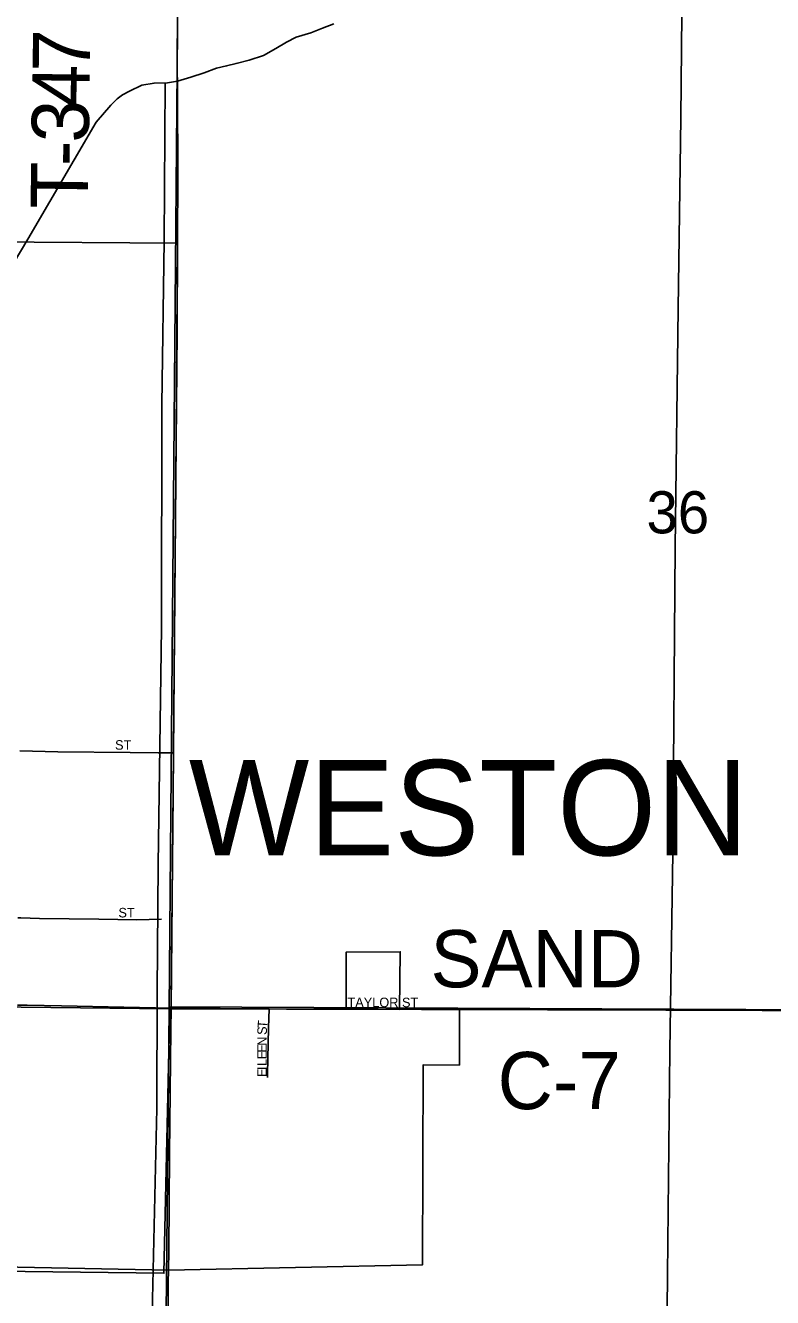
# Model space of a CAD drawing. Extents: x 1443599 to 1910620, y 1028088 to 1361369.
# Drawn here: x 1614403 to 1618321, y 1218862 to 1225536 of the extents above; entities that cross this region are included whole.
import ezdxf

# ---------------------------------------------------------------- set-up
doc = ezdxf.new("R2010")
doc.units = 0
for name, color, linetype in [('GM_X_City_Street', 7, 'Continuous'), ('GM_X_City_Street_Text', 7, 'Continuous'), ('GM_X_Corporation', 7, 'Continuous'), ('GM_X_Corporation_Text', 7, 'Continuous'), ('GM_X_County_Road', 7, 'Continuous'), ('GM_X_County_Road_Text', 7, 'Continuous'), ('GM_X_Minor_River', 7, 'Continuous'), ('GM_X_Section', 7, 'Continuous'), ('GM_X_Section_Text', 7, 'Continuous'), ('GM_X_State_Route', 7, 'Continuous'), ('GM_X_Township', 7, 'Continuous'), ('GM_X_Township_Road_Text', 7, 'Continuous')]:
    doc.layers.add(name, color=color, linetype=linetype)

msp = doc.modelspace()

# ---------------------------------------------------------------- linework, layer by layer
at = {"layer": 'GM_X_City_Street'}
for points in [[(1614372.6, 1221730.2), (1614573.4, 1221725.7), (1614951.5, 1221721.1), (1615099.4, 1221719.8), (1615148.7, 1221719.9), (1615179, 1221720)], [(1614362.1, 1220854.6), (1614379.1, 1220854.3), (1614477, 1220851.2), (1614787.7, 1220847.2), (1614987.8, 1220844), (1615116.2, 1220846.5)], [(1614360.3, 1220396.1), (1614412.1, 1220395.2), (1614592, 1220392.7), (1614919.4, 1220386.2), (1615166.8, 1220380.6)], [(1615671.6, 1220017.2), (1615671.6, 1220033.3), (1615678.1, 1220276.7), (1615681.8, 1220376.3)], [(1616085.3, 1220374.8), (1616136.9, 1220374.5), (1616253.7, 1220374.3), (1616364.3, 1220373.8)]]:
    msp.add_lwpolyline(points, dxfattribs=at)
at = {"layer": 'GM_X_Corporation'}
msp.add_lwpolyline([(1614197, 1224401.7), (1615200.1, 1224394.6), (1615191.8, 1223150.4), (1615179, 1221720), (1615166.8, 1220380.6), (1615681.8, 1220376.3), (1616085.3, 1220374.8), (1616084.9, 1220674.1), (1616368.6, 1220676.3), (1616364.3, 1220373.8), (1616679, 1220375.2), (1616679.2, 1220082.1), (1616488.9, 1220083.4), (1616484.8, 1219033.3), (1615152.7, 1219006.6), (1612518, 1219058.9)], dxfattribs=at)
at = {"layer": 'GM_X_County_Road'}
for points in [[(1615166.8, 1220380.6), (1615213.5, 1220380.2), (1615379.2, 1220378.7), (1615511.8, 1220376.9), (1615681.8, 1220376.3)], [(1615681.8, 1220376.3), (1615772.8, 1220375.9), (1616085.3, 1220374.8)], [(1616364.3, 1220373.8), (1616679.1, 1220375.2)], [(1616679.1, 1220375.2), (1616859.4, 1220374.6), (1617138.4, 1220373.3), (1617368.2, 1220372.1), (1617581.7, 1220372.1), (1617762.2, 1220370.4), (1618123.4, 1220369.7), (1618697.9, 1220362.8), (1618862.2, 1220361.8), (1618928.3, 1220363.4), (1618945.4, 1220365.2)]]:
    msp.add_lwpolyline(points, dxfattribs=at)
at = {"layer": 'GM_X_Minor_River'}
for points in [[(1617853.3, 1226327.9), (1617840.1, 1225049.4), (1617825.5, 1224051.8), (1617810.7, 1222799.8), (1617798, 1221193.2), (1617782.7, 1220157.6), (1617771.2, 1218983.8), (1617758, 1217707.9), (1617748.7, 1216428), (1617736.7, 1215352.4), (1617735.8, 1213978.3), (1617725.2, 1212506.2), (1617715, 1211422.7), (1617702.4, 1210197), (1617703.6, 1209429.7), (1617680.8, 1208428.5), (1617671.9, 1207420.9), (1617660.9, 1206527.6), (1617638.1, 1205167.5)], [(1616020, 1225544.6), (1615961.5, 1225521.6), (1615899, 1225496.6), (1615822.6, 1225473.8), (1615772.1, 1225448.6), (1615715.4, 1225415.5), (1615650.7, 1225378.5), (1615576.2, 1225353.7), (1615507.9, 1225336.8), (1615457.6, 1225323.6), (1615405.3, 1225312.5), (1615340.8, 1225287.5), (1615270.4, 1225264.7), (1615199.9, 1225243.8), (1615147.7, 1225234.7), (1615077.6, 1225233.8), (1615013.4, 1225222.9), (1614948.8, 1225191.9), (1614912.4, 1225172.5)], [(1611444.7, 1220885.3), (1611444.3, 1221099.7), (1611143.6, 1221684), (1611133, 1222970.4), (1611135.9, 1223023.6), (1611156.5, 1223062.1), (1611184.5, 1223072.3), (1611302.9, 1223075.5), (1611951.5, 1223059.9), (1612608.1, 1223046.3), (1613458.9, 1223029.6), (1613668.1, 1223322.5), (1613735.4, 1223275.2), (1614133, 1223943.6), (1614415.2, 1224415.6), (1614773.8, 1225028.6), (1614851.4, 1225117.5), (1614884, 1225151), (1614912.4, 1225172.5)], [(1615135.5, 1225234.5), (1615129.9, 1224405.5), (1615117.6, 1223546.2), (1615116.2, 1222376.2), (1615099.6, 1221134.4), (1615094.5, 1220467.4), (1615092.3, 1219854.4), (1615068.3, 1218777), (1615067.4, 1217637.2), (1615056, 1216713.9), (1615044.3, 1215650.5), (1615036.1, 1214564.9), (1615022.5, 1213507.5), (1615006.2, 1212293.8)]]:
    msp.add_lwpolyline(points, dxfattribs=at)
at = {"layer": 'GM_X_Section'}
for points in [[(1609861.1, 1225754.9), (1615202.5, 1225719.6), (1615157.1, 1220376.3), (1609876.1, 1220436.7), (1609830.1, 1220437.4)], [(1615202.5, 1225719.6), (1620518, 1225686.7), (1620446.9, 1220363.7), (1615157.1, 1220376.3)], [(1615157.1, 1220376.3), (1615104, 1215053), (1609835, 1215109.4), (1609876.1, 1220436.7)], [(1620446.9, 1220363.7), (1620417.2, 1215002), (1619967.5, 1215036.6), (1615104, 1215053), (1615157.1, 1220376.3)]]:
    msp.add_lwpolyline(points, close=True, dxfattribs=at)
at = {"layer": 'GM_X_State_Route'}
for points in [[(1615200.1, 1224394.6), (1615202.2, 1224762.6), (1615200.9, 1225173.1), (1615199.1, 1225353.8), (1615200.5, 1225583.7)], [(1615166.8, 1220380.6), (1615168, 1220616.1), (1615176.8, 1221501.9), (1615179, 1221720), (1615181.3, 1221944.7), (1615184.6, 1222371.2), (1615198.9, 1223929.6), (1615200.1, 1224394.6)], [(1615152.7, 1219006.6), (1615154.4, 1219107.5), (1615158.7, 1219613.6), (1615165.4, 1220266.6), (1615166.8, 1220380.6)], [(1615085.8, 1212392.6), (1615089.7, 1212868.6), (1615093.7, 1213213.2), (1615097.7, 1213672.7), (1615098.4, 1213919), (1615101.7, 1214115.8), (1615107.4, 1214723.1), (1615112.1, 1215055.7), (1615114.1, 1215199), (1615118.6, 1215510.9), (1615125.8, 1215888.3), (1615131.6, 1216495.5), (1615135.6, 1217070), (1615138.4, 1217250.5), (1615145.6, 1218186), (1615151.6, 1218941), (1615152.7, 1219006.6)]]:
    msp.add_lwpolyline(points, dxfattribs=at)
at = {"layer": 'GM_X_Township'}
for points in [[(1618936.9, 1220370.1), (1615159.9, 1220387.8), (1615128.7, 1218989.2), (1612506.9, 1219021.2), (1609877.9, 1219061.7), (1609890.3, 1220443.7), (1609839.9, 1220446.6), (1604546.9, 1220492.4), (1601901.6, 1220535), (1599194, 1220561.1), (1593741, 1220583.6), (1592199, 1220592.6), (1588366.5, 1220614.2), (1588383.5, 1221551.2), (1588462.3, 1225902.2), (1593947.1, 1225870.7), (1595282.7, 1225862.3), (1595353.6, 1231166.2), (1599299.9, 1231150.3), (1599313.7, 1233747.6), (1604642.8, 1233717.2), (1604665.8, 1234694.9)], [(1588234.4, 1188702.7), (1588255.8, 1194003.1), (1588277.4, 1199332.4), (1588320.4, 1204610.1), (1588324.6, 1204799.5), (1588321.6, 1209947.2), (1588321.9, 1210027.8), (1588344.4, 1215354.3), (1588366.5, 1220614.2), (1592199, 1220592.6), (1593741, 1220583.6), (1599194, 1220561.1), (1601901.6, 1220535), (1604546.9, 1220492.4), (1609839.9, 1220446.6), (1609890.3, 1220443.7), (1609877.9, 1219061.7), (1612506.9, 1219021.2), (1615128.7, 1218989.2), (1615159.9, 1220387.8), (1618936.9, 1220370.1)]]:
    msp.add_lwpolyline(points, dxfattribs=at)

# ---------------------------------------------------------------- texts
at = {"layer": 'GM_X_City_Street_Text'}
for s, rotation, p in [('ST', 0.00001, (1614872.9, 1221736.3)), ('ST', 0.00001, (1614890.5, 1220856.4)), ('TAYLOR ST', 0.00001, (1616091.7, 1220385.5)), ('T', 85.51539, (1615669.4, 1220273.9)), ('S', 89.04378, (1615668.8, 1220239.5)), ('N', 89.95627, (1615668.8, 1220182.5)), ('E', 89.95718, (1615668.8, 1220147.3)), ('L', 89.97066, (1615668.7, 1220076.9)), ('E', 89.97267, (1615668.8, 1220112.1)), ('I', 89.95628, (1615668.7, 1220054.9)), ('E', 89.97267, (1615668.7, 1220019.7))]:
    msp.add_text(s, height=50, rotation=rotation, dxfattribs=at).set_placement(p)
at = {"layer": 'GM_X_Corporation_Text'}
msp.add_text('WESTON', height=500, rotation=0.00001, dxfattribs=at).set_placement((1615260.1, 1221182))
at = {"layer": 'GM_X_County_Road_Text'}
for s, p in [('SAND', (1616527.3, 1220489.8)), ('C-7', (1616879.3, 1219850.5))]:
    msp.add_text(s, height=300, rotation=0.00001, dxfattribs=at).set_placement(p)
at = {"layer": 'GM_X_Section_Text'}
msp.add_text('36', height=221, rotation=0.00001, dxfattribs=at).set_placement((1617660.3, 1222871.3))
at = {"layer": 'GM_X_Township_Road_Text'}
for s, rotation, p in [('7', 89.27358, (1614740, 1225290.5)), ('4', 89.15784, (1614737.3, 1225105.1)), ('3', 89.12571, (1614734.5, 1224920.1)), ('-', 89.13355, (1614732.6, 1224796.9)), ('T', 89.12571, (1614729.2, 1224572.5))]:
    msp.add_text(s, height=300, rotation=rotation, dxfattribs=at).set_placement(p)

doc.saveas('drawing.dxf')
